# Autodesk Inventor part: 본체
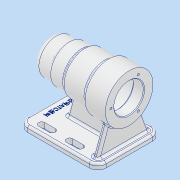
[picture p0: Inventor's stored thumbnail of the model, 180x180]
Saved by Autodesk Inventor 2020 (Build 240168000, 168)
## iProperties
Created: 2021-10
Part Number: 본체
Material: 알루미늄 6061
Document SubType Name: Modeling
Designer: user
Density: 2.7 g/cm^3
Appearance: 알루미늄 - 평지
Mass: 691.173 g
Surface Area: 699.007 cm^2
Volume: 255.99 cm^3
Author: user
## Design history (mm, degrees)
sketch "스케치1"
  geometry: L1 (0, 0)-(0, 25); L2 (0, 25)-(24, 25); L3 (24, 25)-(24, 27); L4 (24, 27)-(46, 27); L5 (46, 27)-(46, 30); L6 (46, 30)-(80, 30); L7 (80, 30)-(80, 34); L8 (80, 34)-(112, 34); L9 (112, 34)-(112, 21); L10 (112, 21)-(97, 21); L11 (97, 21)-(97, 24); L12 (97, 24)-(43, 24); L13 (43, 24)-(43, 21); L14 (43, 21)-(31, 21); L15 (31, 21)-(31, 17.5); L16 (31, 17.5)-(13, 17.5); L17 (13, 17.5)-(13, 16); L18 (13, 16)-(9, 16); L19 (9, 16)-(9, 10.5); L20 (9, 10.5)-(6, 10.5); L21 (6, 10.5)-(6, 0); L22 (6, 0)-(0, 0)
  constraints: 44 end point, 17 perpendicular, 3 vertical, 1 horizontal, 1 parallel
  dimensions: "d0" = 112 distance between parallel lines of L9 L1; "d1" = 24 distance of L1.end L2.end; "d2" = 46 distance between parallel lines of L5 L1; "d3" = 80 distance between parallel lines of L7 L1; "d5" = 34 distance between parallel lines of L22 L8; "d6" = 21 distance between parallel lines of L22 L10; "d7" = 24 distance between parallel lines of L22 L12; "d8" = 21 distance between parallel lines of L22 L14; "d9" = 17.5 distance between parallel lines of L22 L16; "d10" = 16 distance between parallel lines of L22 L18; "d11" = 10.5 distance between parallel lines of L22 L20; "d12" = 25 distance of L1.start L1.end; "d13" = 27 distance between parallel lines of L22 L4; "d14" = 30 distance between parallel lines of L22 L6; "d15" = 15 horizontal distance of L9.end L11.end; "d16" = 54 distance of L11.end L12.end; "d17" = 12 distance of L13.end L14.end; "d18" = 18 distance of L15.end L16.end; "d19" = 4 distance from line of L17.end L19; "d20" = 3 distance from line of L19.end L21
revolve "회전1" sketch "스케치1" stored, may be unused: angle "d21" = 90 deg
node "작업 평면1"
sketch "스케치2"
  geometry: L1 (0, -45)-(-112, -45); L2 (-112, -45)-(-112, 45); L3 (-112, 45)-(0, 45); L4 (0, 45)-(0, -45); L5 (0, -45)-(-112, 45); L6 (-112, -45)-(0, 45); L7 (-112, 34)-(-112, -34) reference; L8 (0, 25)-(0, -25) reference; 4 further points
  constraints: 12 end point, 4 midpoint, 2 parallel, 1 coincident, 1 collinear, 1 horizontal, 1 perpendicular
  dimensions: "d23" = 112 distance of L2.end L3.end; "d24" = 90 distance of L1.end L2.end
extrude "돌출1" join sketch "스케치2" distance "d25" = 8; taper "d26" = 0 deg
sketch "스케치3"
  geometry: L1 (27, 4)-(104, 4); L2 (104, 4)-(104, -4); L3 (104, -4)-(27, -4); L4 (27, -4)-(27, 4); L5 (27, 4)-(104, -4); L6 (104, 4)-(27, -4); L7 (112, -45)-(112, 45) reference; 3 further points
  constraints: 12 end point, 3 midpoint, 2 parallel, 1 horizontal, 1 horizontal alignment, 1 perpendicular
  dimensions: "d27" = 8 distance of L1.end L2.end; "d29" = 77 distance of L2.end L3.end; "d30" = 8 distance between parallel lines of L7 L2
extrude "돌출2" join sketch "스케치3" stored distance "d31" = 8; taper "d32" = 0 deg
node "작업 평면2"
sketch "스케치4"
  geometry: L1 (-62, 45)-(-62, -45) reference; L2 (-24.658, 23.409)-(-62, 37); L3 (-70, 45)-(-62, 45) reference; A1 r 34 centre (0, 0) between (-33.764, -4) and (-33.764, 4) reference; 1 further point
  constraints: 2 end point, 1 point on circle, 1 point on line
  dimensions: "d34" = 110 deg angle of L1 L2; "d94" = 8 distance from line of L2.end L3
feature "리브1" sketch "스케치4" dims "d35" = 1, "d36" = 8, "d37" = 0, "d38" = 0, "d39" = 1, "d40" = 1
sketch "스케치5"
  geometry: L1 (20, -33)-(35, -33); L2 (20, -37.5)-(35, -37.5); L3 (35, -28.5)-(20, -28.5); L4 (0, 45)-(0, -45) reference; L5 (60, -33)-(75, -33); L6 (60, -37.5)-(75, -37.5); L7 (75, -28.5)-(60, -28.5); L8 (20, 33)-(35, 33); L9 (20, 28.5)-(35, 28.5); L10 (35, 37.5)-(20, 37.5); L11 (60, 33)-(75, 33); L12 (60, 28.5)-(75, 28.5); L13 (75, 37.5)-(60, 37.5); A1 r 4.5 centre (20, -33) between (20, -28.5) and (20, -37.5); A2 r 4.5 centre (35, -33) between (35, -37.5) and (35, -28.5); A3 r 4.5 centre (60, -33) between (60, -28.5) and (60, -37.5); A4 r 4.5 centre (75, -33) between (75, -37.5) and (75, -28.5); A5 r 4.5 centre (20, 33) between (20, 37.5) and (20, 28.5); A6 r 4.5 centre (35, 33) between (35, 28.5) and (35, 37.5); A7 r 4.5 centre (60, 33) between (60, 37.5) and (60, 28.5); A8 r 4.5 centre (75, 33) between (75, 28.5) and (75, 37.5); 5 further points
  constraints: 32 end point, 16 point on circle, 16 tangent, 8 centre point, 4 horizontal, 4 midpoint, 4 parallel, 2 vertical alignment
  dimensions: "d41" = 15 distance of L1.start L1.end; "d42" = 9 diameter of A2; "d43" = 20 distance from line of L4 L1.start; "d44" = 15 distance of L5.start L5.end; "d45" = 9 diameter of A4; "d46" = 25 distance of L5.start L1.end; "d47" = 15 distance of L8.start L8.end; "d48" = 9 diameter of A6; "d49" = 33 vertical distance of point (27.5, -33) point (0, 0); "d50" = 33 vertical distance of point (0, 0) point (27.5, 33); "d51" = 33 vertical distance of point (0, 0) point (67.5, -33); "d52" = 15 distance of L11.start L11.end; "d53" = 9 diameter of A8; "d54" = 33 vertical distance of point (0, 0) point (67.5, 33)
extrude "돌출3" cut sketch "스케치5" distance "d55" = 50; taper "d56" = 0 deg
sketch "스케치6"
  geometry: 2 further points
  constraints: 1 horizontal alignment
  dimensions: "d57" = 26 distance of point (0, 0) point (-26, 0)
hole "구멍1" sketch "스케치6" at (-26, 0) diameter "d58" = 3.242; stored, may be unused: countersink angle "d62" = 90 deg, drill point angle "d64" = 118 deg; dims "d59" = 8, "d60" = 4, "d61" = 2, "d63" = 11
sketch "스케치7"
  geometry: L1 (0, 45)-(0, -45) reference; 3 further points
  constraints: 1 horizontal alignment, 1 midpoint, 1 other
  dimensions: "d71" = 12 distance from line of point (12, 0) L1
feature "엠보싱1" sketch "스케치7" dims "d15" = 15, "d72" = 0.5, "d73" = 0
fillet "모깎기1" dims "d74" = 12
fillet "모깎기2" dims "d75" = 3
fillet "모깎기5" dims "d78" = 8
fillet "모깎기6" dims "d79" = 3
fillet "모깎기7" dims "d80" = 0.3
fillet "모깎기8" dims "d81" = 0.3
fillet "모깎기9" dims "d82" = 3
fillet "모깎기10" dims "d83" = 3
chamfer "모따기1" distance "d84" = 1; stored, may be unused: second distance "d85" = 2, angle "d86" = 45 deg
fillet "모깎기12" dims "d88" = 3
feature "면 기울기1" dims angle "d89" = 15 deg
fillet "모깎기13" dims "d90" = 3
fillet "모깎기14" dims "d91" = 3
fillet "모깎기15" dims "d92" = 3
fillet "모깎기16" dims "d93" = 3
node "솔리드1"
mirror "미러1"
pattern_circular "원형 패턴1" dims angle "d66" = 120 deg
pattern_circular "원형 패턴2" dims angle "d69" = -120 deg
feature "A9D066F2-1C7D-4E18-AEED-F7BC21143FA4" dims "d58" = 3.242, "d59" = 8, "d60" = 4, "d61" = 2, "d62" = 90 deg, "d63" = 11, "d64" = 118 deg
other parameters: "d33" = 104
